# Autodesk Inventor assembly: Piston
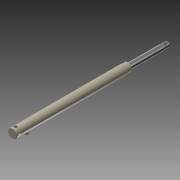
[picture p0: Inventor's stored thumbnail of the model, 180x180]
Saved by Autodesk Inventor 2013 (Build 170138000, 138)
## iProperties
Created: 2015-07
Part Number: Piston
Document SubType Name: Assembly
Designer: OL
Author: OL
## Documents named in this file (3)
- J:\SAUVEGARDE 2013 Juillet\OL1 (U)\TRAVAUX\2014-2015\u11 sujet bac\Modele Grue rotative\Piston.iam
- J:\SAUVEGARDE 2013 Juillet\OL1 (U)\TRAVAUX\2014-2015\u11 sujet bac\Modele Grue rotative\pompe\Verin630-5-corps.ipt
- J:\SAUVEGARDE 2013 Juillet\OL1 (U)\TRAVAUX\2014-2015\u11 sujet bac\Modele Grue rotative\pompe\Verin630-5-tige.ipt
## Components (2 placed, 2 different names)
1. Verin630-5-corps:1 — Tangente:1, Placage:1
2. Verin630-5-tige:1 — Tangente:1, Placage:1
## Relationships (2: Tangent 1, Mate 1)
- Tangente:1: Verin630-5-corps:1 ↔ Verin630-5-tige:1
- Placage:1 [Mate]: Verin630-5-corps:1 ↔ Verin630-5-tige:1
